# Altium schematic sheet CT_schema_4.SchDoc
size 368 x 245 mm
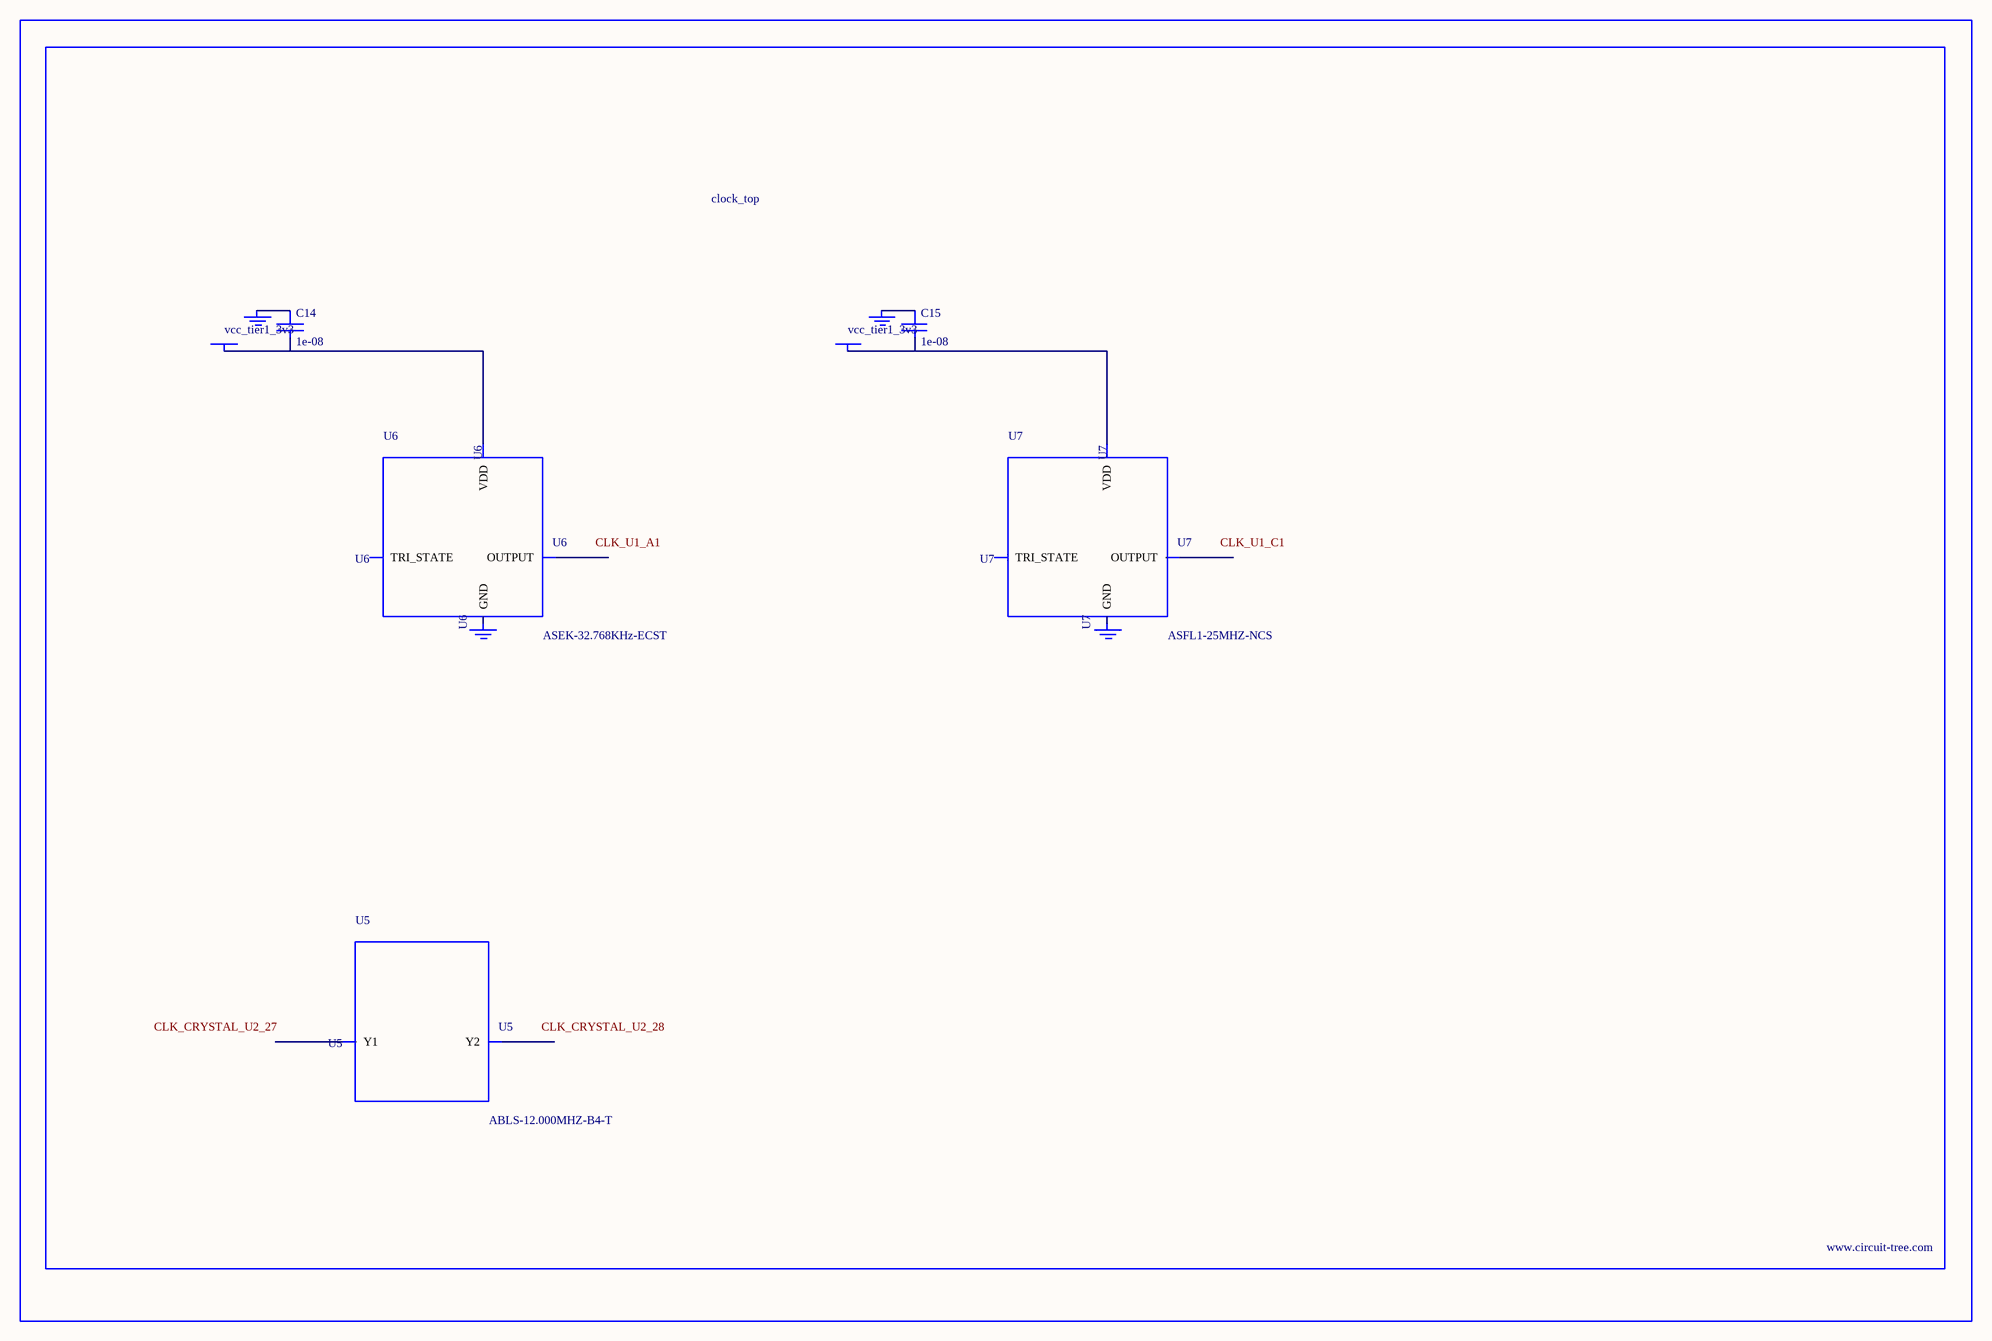
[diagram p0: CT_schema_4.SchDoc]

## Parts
BORDER3  (no value)
C14  1e-08  [C0402]
C15  1e-08  [C0402]
GND_INSTANCE_3_0  (no value)
GND_INSTANCE_3_1  (no value)
GND_INSTANCE_3_2  (no value)
GND_INSTANCE_3_3  (no value)
POWER_INSTANCE_3_0  vcc_tier1_3v3
POWER_INSTANCE_3_1  vcc_tier1_3v3
U5  ABLS-12.000MHZ-B4-T  [ABLS-12.000MHZ-B4-T]
U6  ASEK-32.768KHz-ECST  [ASEK]
U7  ASFL1-25MHZ-NCS  [ASFL1]

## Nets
NetC14_1: C14.1 GND_INSTANCE_3_0.0(GND)
NetC14_2: C14.2 POWER_INSTANCE_3_0.0(PWR) U6.4(VDD)
NetC15_1: C15.1 GND_INSTANCE_3_2.0(GND)
NetC15_2: C15.2 POWER_INSTANCE_3_1.0(PWR) U7.4(VDD)

Not connected (* = marked no-connect by the designer): GND_INSTANCE_3_1 0(GND); GND_INSTANCE_3_3 0(GND); U5 1(Y1) 2(Y2); U6 1(TRI_STATE) 2(GND) 3(OUTPUT); U7 1(TRI_STATE) 2(GND) 3(OUTPUT)

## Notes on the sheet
- Labels drawn without touching a wire or pin: CLK_CRYSTAL_U2_27, CLK_CRYSTAL_U2_28, CLK_U1_A1, CLK_U1_C1

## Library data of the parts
BORDER3 = BORDER_PAGE3
C14 C15 = C0402C103K3RAC
GND_INSTANCE_3_0-GND_INSTANCE_3_3 = GND
POWER_INSTANCE_3_0 POWER_INSTANCE_3_1 = PWR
